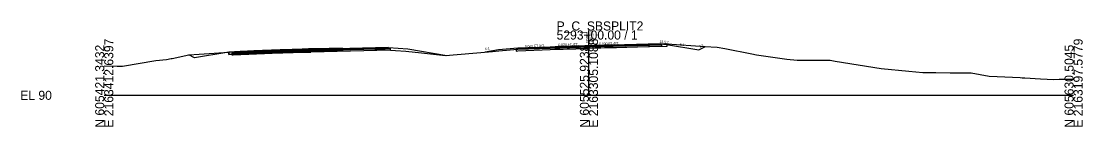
# Model space of a CAD drawing. Extents: x -26 to 1303, y -10 to 12033.
# Drawn here: x -25.7 to 302.8, y 6990.3 to 7022.8 of the extents above; entities that cross this region are included whole.
import ezdxf

# ---------------------------------------------------------------- set-up
doc = ezdxf.new("R2010")
doc.units = 0
for name, color, linetype in [('RD_GPK_XS_Cell', 7, 'Continuous'), ('RD_XS_Base', 7, 'Continuous'), ('RD_XS_ExGround', 7, 'Continuous'), ('RD_XS_ExPaveRet', 7, 'Continuous'), ('RD_XS_Greenside', 7, 'Continuous'), ('RD_XS_Pave', 7, 'Continuous'), ('RD_XS_PaveOvlay_CP', 7, 'Continuous'), ('RD_XS_TieSlope', 7, 'Continuous'), ('RD_XS_TX_Elev_EX', 7, 'Continuous'), ('RD_XS_TX_Elev_PR', 7, 'Continuous'), ('RD_XS_TX_ShdSlope', 7, 'Continuous'), ('RD_XS_TX_Slope', 7, 'Continuous')]:
    doc.layers.add(name, color=color, linetype=linetype)

msp = doc.modelspace()

# ---------------------------------------------------------------- linework, layer by layer
at = {"layer": 'RD_GPK_XS_Cell'}
for p, q in [((150, 7000), (150, 7020)), ((0, 7000), (150, 7000)), ((150, 7000), (300, 7000))]:
    msp.add_line(p, q, dxfattribs=at)
at = {"layer": 'RD_XS_Base'}
for p, q in [((63.95, 7013.83), (88.45, 7014.46)), ((87.95, 7014.45), (87.95, 7014.45)), ((87.95, 7014.45), (87.95, 7014.45)), ((87.95, 7014.45), (87.95, 7014.45)), ((88.45, 7014.46), (88.45, 7013.96)), ((88.45, 7014.43), (88.45, 7014.43)), ((128, 7014.19), (127.5, 7014.17)), ((138, 7014.59), (128, 7014.19)), ((128, 7014.19), (128, 7014.19)), ((136, 7014.51), (136, 7014.51)), ((150, 7014.92), (138, 7014.59)), ((138, 7014.09), (150, 7014.42)), ((150, 7014.92), (172, 7015.54)), ((150, 7014.42), (150, 7015.08)), ((150, 7015.08), (150, 7015.08)), ((150, 7015.08), (150, 7015.08)), ((150, 7015.08), (150, 7014.92)), ((172.5, 7015.05), (150, 7014.42)), ((150, 7014.92), (150, 7014.92)), ((150, 7014.42), (150, 7014.92)), ((150, 7014.92), (150, 7014.92)), ((150, 7014.92), (150, 7014.92)), ((150, 7014.42), (150, 7014.42)), ((162, 7015.26), (162, 7015.26)), ((162, 7015.26), (162, 7015.26)), ((162, 7014.76), (162, 7014.76)), ((162, 7014.76), (162, 7014.76)), ((172, 7015.54), (172, 7015.54)), ((172.5, 7015.55), (172.5, 7015.05)), ((172.5, 7015.52), (172.5, 7015.52)), ((39.84, 7013.03), (39.45, 7013.02)), ((39.45, 7013.02), (39.45, 7012.91)), ((39.45, 7012.91), (39.45, 7012.52)), ((39.45, 7012.52), (39.84, 7012.53)), ((39.95, 7013.04), (39.84, 7013.03)), ((39.84, 7012.53), (39.95, 7012.54)), ((49.56, 7013.42), (39.95, 7013.04)), ((39.95, 7012.54), (49.56, 7012.92)), ((51.95, 7013.52), (49.56, 7013.42)), ((49.56, 7012.92), (51.95, 7013.02)), ((61.74, 7013.77), (51.95, 7013.52)), ((51.95, 7013.02), (61.74, 7013.27)), ((63.95, 7013.83), (61.74, 7013.77)), ((61.74, 7013.27), (63.95, 7013.33)), ((63.95, 7013.33), (63.95, 7013.99)), ((63.95, 7013.99), (63.95, 7013.99)), ((63.95, 7013.99), (63.95, 7013.99)), ((63.95, 7013.99), (63.95, 7013.83)), ((88.45, 7013.96), (63.95, 7013.33)), ((63.95, 7013.83), (63.95, 7013.83)), ((63.95, 7013.33), (63.95, 7013.83)), ((63.95, 7013.83), (63.95, 7013.83)), ((63.95, 7013.83), (63.95, 7013.83)), ((63.95, 7013.33), (63.95, 7013.33)), ((87.95, 7013.95), (87.95, 7013.95)), ((87.95, 7013.95), (87.95, 7013.95)), ((127.5, 7014.17), (127.5, 7014.17)), ((127.5, 7014.17), (127.5, 7013.67)), ((127.5, 7013.67), (128, 7013.69)), ((128, 7013.69), (138, 7014.09)), ((128, 7013.69), (128, 7013.69)), ((136, 7014.01), (136, 7014.01))]:
    msp.add_line(p, q, dxfattribs=at)
at = {"layer": 'RD_XS_ExGround'}
msp.add_lwpolyline([(0, 7009.09), (3.99, 7008.99), (5.69, 7008.97), (16, 7010.73), (19.25, 7011.08), (20.7, 7011.32), (21.02, 7011.38), (26.18, 7012.48), (29.34, 7012.69), (38.53, 7013.35), (44.37, 7013.66), (54.41, 7014.01), (58.18, 7014.09), (61.22, 7014.23), (63.48, 7014.31), (66.11, 7014.38), (73.77, 7014.57), (83.78, 7014.28), (93.37, 7013.65), (98.15, 7013.1), (105.61, 7012.25), (118.89, 7013.42), (119.74, 7013.5), (120.15, 7013.54), (122.15, 7013.71), (129.15, 7014.34), (129.87, 7014.39), (130.57, 7014.43), (136.01, 7014.78), (138.71, 7014.94), (138.91, 7014.95), (139.52, 7014.98), (140.49, 7015.02), (148.72, 7015.29), (154.77, 7015.48), (154.88, 7015.49), (155.14, 7015.49), (155.14, 7015.49), (155.15, 7015.49), (155.36, 7015.5), (155.94, 7015.51), (157.21, 7015.5), (157.9, 7015.5), (158.51, 7015.51), (164.99, 7015.7), (168.39, 7015.77), (174.21, 7015.89), (185.92, 7015.06), (189.66, 7014.81), (192.07, 7014.43), (200.42, 7012.84), (201.87, 7012.5), (211.26, 7011.2), (214.46, 7010.83), (223.87, 7010.89), (224.62, 7010.85), (226.24, 7010.57), (240.45, 7008.26), (249.04, 7007.43), (253.34, 7007.08), (257.39, 7007.08), (261.82, 7006.97), (262.56, 7006.94), (267.01, 7006.96), (268.34, 7006.9), (273.88, 7005.93), (276.35, 7005.84), (283.46, 7005.51), (284.11, 7005.44), (284.9, 7005.39), (289.72, 7005.06), (293.84, 7004.89), (295.54, 7004.97), (298.45, 7004.95), (300, 7004.99)], dxfattribs=at)
at = {"layer": 'RD_XS_ExPaveRet'}
for points in [[(73.77, 7014.57), (73.77, 7014.57), (73.77, 7014.1), (73.77, 7013.82), (73.77, 7013.82), (73.77, 7013.82), (69.56, 7013.72), (66.11, 7013.63), (63.79, 7013.57), (63.48, 7013.56), (63.21, 7013.56), (61.22, 7013.48), (59.6, 7013.41), (58.18, 7013.34), (56.38, 7013.3), (54.41, 7013.26), (46.34, 7012.98), (44.37, 7012.91), (42.08, 7012.79), (38.53, 7012.6), (38.53, 7012.82), (38.53, 7013.35), (42.08, 7013.54), (44.37, 7013.66), (46.34, 7013.73), (54.41, 7014.01), (56.38, 7014.05), (58.18, 7014.09), (59.6, 7014.16), (61.22, 7014.23), (63.21, 7014.31), (63.48, 7014.31), (63.79, 7014.32), (66.11, 7014.38), (69.56, 7014.47), (73.77, 7014.57), (73.77, 7014.57)], [(69.56, 7014.47), (66.11, 7014.38), (63.79, 7014.32), (63.48, 7014.31), (63.21, 7014.31), (61.22, 7014.23), (59.6, 7014.16), (58.18, 7014.09), (56.38, 7014.05), (54.41, 7014.01), (46.34, 7013.73), (44.37, 7013.66), (42.08, 7013.54), (38.53, 7013.35), (38.53, 7012.82), (38.53, 7012.6), (42.08, 7012.79), (44.37, 7012.91), (46.34, 7012.98), (54.41, 7013.26), (56.38, 7013.3), (58.18, 7013.34), (59.6, 7013.41), (61.22, 7013.48), (63.21, 7013.56), (63.48, 7013.56), (63.79, 7013.57), (66.11, 7013.63), (69.56, 7013.72), (73.77, 7013.82), (73.77, 7014.1), (73.77, 7014.57), (69.56, 7014.47)], [(174.21, 7015.89), (174.21, 7015.89), (168.39, 7015.77), (168.39, 7015.77), (164.99, 7015.7), (164.99, 7015.7), (158.51, 7015.51), (158.51, 7015.51), (158.51, 7015.51), (157.9, 7015.5), (157.21, 7015.5), (155.94, 7015.51), (155.36, 7015.5), (155.36, 7015.5), (155.15, 7015.49), (155.14, 7015.49), (155.14, 7015.49), (154.88, 7015.49), (154.77, 7015.48), (154.77, 7015.48), (148.72, 7015.29), (148.72, 7015.29), (148.72, 7015.29), (140.49, 7015.02), (140.49, 7015.02), (139.52, 7014.98), (139.52, 7014.98), (139.52, 7014.98), (139.52, 7014.23), (139.52, 7014.23), (140.49, 7014.27), (140.49, 7014.27), (148.72, 7014.54), (148.72, 7014.54), (148.72, 7014.54), (154.77, 7014.73), (154.77, 7014.73), (154.88, 7014.74), (155.14, 7014.74), (155.14, 7014.74), (155.15, 7014.74), (155.36, 7014.75), (155.36, 7014.75), (155.94, 7014.76), (157.21, 7014.75), (157.9, 7014.75), (158.51, 7014.76), (158.51, 7014.76), (158.51, 7014.76), (164.99, 7014.95), (164.99, 7014.95), (168.39, 7015.02), (168.39, 7015.02), (174.21, 7015.14), (174.21, 7015.14), (174.21, 7015.14), (174.21, 7015.89), (174.21, 7015.89), (174.21, 7015.89)], [(174.21, 7015.89), (168.39, 7015.77), (164.99, 7015.7), (158.51, 7015.51), (157.9, 7015.5), (157.21, 7015.5), (155.94, 7015.51), (155.36, 7015.5), (155.15, 7015.49), (155.14, 7015.49), (155.14, 7015.49), (154.88, 7015.49), (154.77, 7015.48), (148.72, 7015.29), (140.49, 7015.02), (139.52, 7014.98), (139.52, 7014.98), (139.52, 7014.23), (139.52, 7014.23), (140.49, 7014.27), (148.72, 7014.54), (154.77, 7014.73), (154.88, 7014.74), (155.14, 7014.74), (155.14, 7014.74), (155.15, 7014.74), (155.36, 7014.75), (155.94, 7014.76), (157.21, 7014.75), (157.9, 7014.75), (158.51, 7014.76), (164.99, 7014.95), (168.39, 7015.02), (174.21, 7015.14), (174.21, 7015.89)]]:
    msp.add_lwpolyline(points, dxfattribs=at)
at = {"layer": 'RD_XS_Greenside'}
for p, q in [((93.95, 7014.29), (105.99, 7012.28)), ((174, 7015.7), (184, 7014.03)), ((184, 7014.03), (186.05, 7015.05)), ((27.95, 7011.53), (26.13, 7012.44)), ((37.95, 7013.19), (27.95, 7011.53)), ((122, 7014.02), (117.85, 7013.33))]:
    msp.add_line(p, q, dxfattribs=at)
at = {"layer": 'RD_XS_Pave'}
for p, q in [((87.95, 7014.77), (63.95, 7014.15)), ((87.95, 7014.61), (63.95, 7013.99)), ((63.95, 7013.99), (87.95, 7014.61)), ((63.95, 7013.83), (87.95, 7014.45)), ((87.95, 7014.61), (87.95, 7014.77)), ((87.95, 7014.77), (87.95, 7014.77)), ((87.95, 7014.77), (87.95, 7014.77)), ((87.95, 7014.77), (87.95, 7014.77)), ((87.95, 7014.45), (87.95, 7014.61)), ((87.95, 7014.61), (87.95, 7014.61)), ((87.95, 7014.61), (87.95, 7014.61)), ((87.95, 7014.61), (87.95, 7014.61)), ((87.95, 7014.61), (87.95, 7014.61)), ((87.95, 7014.61), (87.95, 7014.61)), ((87.95, 7014.45), (87.95, 7014.45)), ((87.95, 7014.45), (87.95, 7014.45)), ((138, 7014.9), (128, 7014.5)), ((128, 7014.35), (138, 7014.74)), ((138, 7014.74), (128, 7014.35)), ((128, 7014.19), (138, 7014.59)), ((128, 7014.5), (128, 7014.5)), ((128, 7014.5), (128, 7014.35)), ((128, 7014.35), (128, 7014.35)), ((128, 7014.35), (128, 7014.19)), ((136, 7014.82), (136, 7014.82)), ((136, 7014.66), (136, 7014.66)), ((136, 7014.66), (136, 7014.66)), ((136, 7014.51), (136, 7014.51)), ((150, 7015.24), (138, 7014.9)), ((138, 7014.74), (150, 7015.08)), ((150, 7015.08), (138, 7014.74)), ((138, 7014.59), (150, 7014.92)), ((172, 7015.86), (150, 7015.24)), ((172, 7015.7), (150, 7015.08)), ((150, 7015.08), (172, 7015.7)), ((150, 7014.92), (172.5, 7015.55)), ((150, 7015.24), (150, 7015.24)), ((150, 7015.08), (150, 7015.08)), ((150, 7015.08), (150, 7015.08)), ((150, 7015.08), (150, 7014.92)), ((150, 7015.08), (150, 7015.08)), ((150, 7014.92), (150, 7015.08)), ((150, 7015.08), (150, 7015.08)), ((150, 7015.08), (150, 7015.08)), ((150, 7014.92), (150, 7014.92)), ((150, 7014.92), (150, 7014.92)), ((162, 7015.58), (162, 7015.58)), ((162, 7015.58), (162, 7015.58)), ((162, 7015.42), (162, 7015.42)), ((162, 7015.42), (162, 7015.42)), ((162, 7015.42), (162, 7015.42)), ((162, 7015.42), (162, 7015.42)), ((162, 7015.26), (162, 7015.26)), ((162, 7015.26), (162, 7015.26)), ((172, 7015.7), (172, 7015.86)), ((172, 7015.86), (172, 7015.86)), ((172, 7015.54), (172, 7015.7)), ((172, 7015.7), (172, 7015.7)), ((49.56, 7013.74), (39.95, 7013.35)), ((39.95, 7013.2), (49.56, 7013.58)), ((49.56, 7013.58), (39.95, 7013.2)), ((39.95, 7013.04), (49.56, 7013.42)), ((39.95, 7013.35), (39.95, 7013.32)), ((39.95, 7013.32), (39.95, 7013.2)), ((39.95, 7013.2), (39.95, 7013.16)), ((39.95, 7013.16), (39.95, 7013.04)), ((51.95, 7013.83), (49.56, 7013.74)), ((49.56, 7013.58), (51.95, 7013.67)), ((51.95, 7013.67), (49.56, 7013.58)), ((49.56, 7013.42), (51.95, 7013.52)), ((61.74, 7014.09), (51.95, 7013.83)), ((51.95, 7013.67), (61.74, 7013.93)), ((61.74, 7013.93), (51.95, 7013.67)), ((51.95, 7013.52), (61.74, 7013.77)), ((63.95, 7014.15), (61.74, 7014.09)), ((61.74, 7013.93), (63.95, 7013.99)), ((63.95, 7013.99), (61.74, 7013.93)), ((61.74, 7013.77), (63.95, 7013.83)), ((63.95, 7014.15), (63.95, 7014.15)), ((63.95, 7013.99), (63.95, 7013.99)), ((63.95, 7013.99), (63.95, 7013.99)), ((63.95, 7013.99), (63.95, 7013.83)), ((63.95, 7013.99), (63.95, 7013.99)), ((63.95, 7013.83), (63.95, 7013.99)), ((63.95, 7013.99), (63.95, 7013.99)), ((63.95, 7013.99), (63.95, 7013.99)), ((63.95, 7013.83), (63.95, 7013.83)), ((63.95, 7013.83), (63.95, 7013.83))]:
    msp.add_line(p, q, dxfattribs=at)
at = {"layer": 'RD_XS_PaveOvlay_CP'}
for p, q in [((87.95, 7014.77), (63.95, 7014.15)), ((87.95, 7014.77), (87.95, 7014.77)), ((87.95, 7014.77), (87.95, 7014.77)), ((138, 7014.9), (128, 7014.5)), ((136, 7014.82), (136, 7014.82)), ((150, 7015.24), (138, 7014.9)), ((172, 7015.86), (150, 7015.24)), ((150, 7015.24), (150, 7015.24)), ((162, 7015.58), (162, 7015.58)), ((162, 7015.58), (162, 7015.58)), ((49.56, 7013.74), (39.95, 7013.35)), ((51.95, 7013.83), (49.56, 7013.74)), ((61.74, 7014.09), (51.95, 7013.83)), ((63.95, 7014.15), (61.74, 7014.09)), ((63.95, 7014.15), (63.95, 7014.15))]:
    msp.add_line(p, q, dxfattribs=at)
at = {"layer": 'RD_XS_TieSlope'}
for p, q in [((87.95, 7014.77), (93.95, 7014.29)), ((128, 7014.5), (122, 7014.02)), ((172, 7015.86), (174, 7015.7)), ((39.95, 7013.35), (37.95, 7013.19))]:
    msp.add_line(p, q, dxfattribs=at)

# ---------------------------------------------------------------- texts
at = {"layer": 'RD_GPK_XS_Cell'}
for s, p in [('P_C_SBSPLIT2', (140, 7020)), ('5293+00.00 / 1', (140, 7017.2)), ('EL 90', (-26, 6998.6))]:
    msp.add_text(s, height=2.8, dxfattribs=at).set_placement(p)
for s, p in [('N 605421.3432', (0, 6990)), ('E 2163412.6397', (2.8, 6990)), ('N 605525.9238', (150, 6990)), ('E 2163305.1088', (152.8, 6990)), ('N 605630.5045', (300, 6990)), ('E 2163197.5779', (302.8, 6990))]:
    msp.add_text(s, height=2.8, rotation=90, dxfattribs=at).set_placement(p)
at = {"layer": 'RD_XS_TX_Elev_EX'}
msp.add_text('105.33', height=0.6, rotation=90, dxfattribs=at).set_placement((149.73, 7016.17))
at = {"layer": 'RD_XS_TX_Elev_PR'}
msp.add_text('105.24', height=1, rotation=90, dxfattribs=at).set_placement((151.41, 7015.67))
at = {"layer": 'RD_XS_TX_ShdSlope'}
msp.add_text('12.5:1', height=0.75, rotation=355.4261, dxfattribs=at).set_placement((171.84, 7016.2))
at = {"layer": 'RD_XS_TX_Slope'}
for s, rotation, p in [('6:1', 9.4642, (117.94, 7013.9)), ('0.040 FT./FT.', 2.2906, (130.15, 7014.72)), ('0.030 FT./FT.', 1.7184, (140.58, 7015.23)), ('0.030 FT./FT.', 1.7184, (153.16, 7015.51)), ('6:1', 350.5358, (178.13, 7015.39)), ('2:1', 26.5651, (184.32, 7014.61))]:
    msp.add_text(s, height=0.75, rotation=rotation, dxfattribs=at).set_placement(p)

doc.saveas('drawing.dxf')
